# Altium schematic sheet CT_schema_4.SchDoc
size 205 x 169 mm
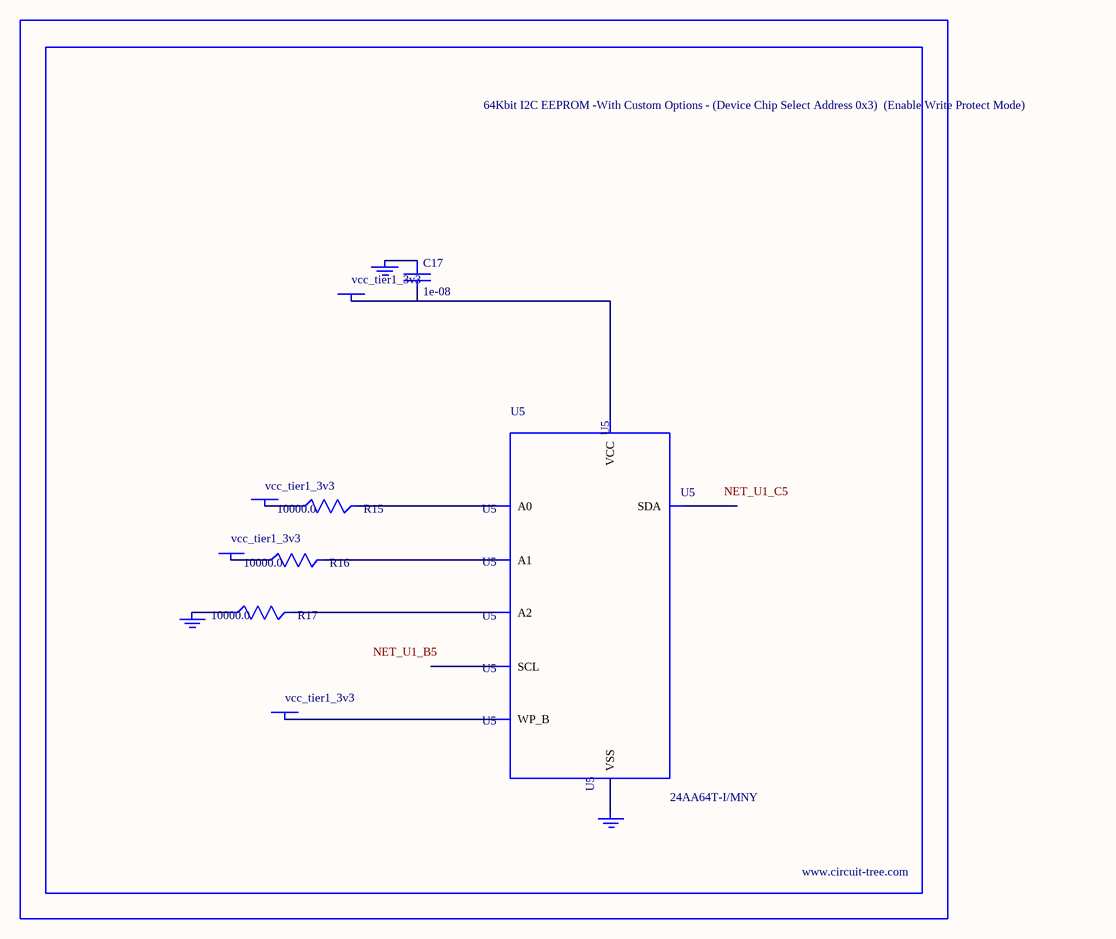
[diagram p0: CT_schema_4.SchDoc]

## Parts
BORDER3  (no value)
C17  1e-08  [C0402]
GND_INSTANCE_3_0  (no value)
GND_INSTANCE_3_1  (no value)
GND_INSTANCE_3_2  (no value)
POWER_INSTANCE_3_0  vcc_tier1_3v3
POWER_INSTANCE_3_1  vcc_tier1_3v3
POWER_INSTANCE_3_2  vcc_tier1_3v3
POWER_INSTANCE_3_3  vcc_tier1_3v3
R15  10000.0  [R0603]
R16  10000.0  [R0603]
R17  10000.0  [R0603]
U5  24AA64T-I/MNY  [TDFN-8/6MM]

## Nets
NetC17_1: C17.1 GND_INSTANCE_3_1.0(GND)
NetC17_2: C17.2 POWER_INSTANCE_3_3.0(PWR) U5.8(VCC)
NetGND_INSTANCE_3_0_0: GND_INSTANCE_3_0.0(GND) R17.1
NetGND_INSTANCE_3_2_0: GND_INSTANCE_3_2.0(GND) U5.4(VSS)
NetPOWER_INSTANCE_3_0_0: POWER_INSTANCE_3_0.0(PWR) R15.1
NetPOWER_INSTANCE_3_1_0: POWER_INSTANCE_3_1.0(PWR) R16.1
NetPOWER_INSTANCE_3_2_0: POWER_INSTANCE_3_2.0(PWR) U5.7(WP_B)
NetR15_2: R15.2 U5.1(A0)
NetR16_2: R16.2 U5.2(A1)
NetR17_2: R17.2 U5.3(A2)

Not connected (* = marked no-connect by the designer): U5 5(SDA) 6(SCL)

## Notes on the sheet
- Labels drawn without touching a wire or pin: NET_U1_B5, NET_U1_C5

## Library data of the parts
BORDER3 = BORDER_PAGE3
C17 = C0402C103K3RAC
GND_INSTANCE_3_0-GND_INSTANCE_3_2 = GND
POWER_INSTANCE_3_0-POWER_INSTANCE_3_3 = PWR
R15-R17 = RC0603JR-0710KL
